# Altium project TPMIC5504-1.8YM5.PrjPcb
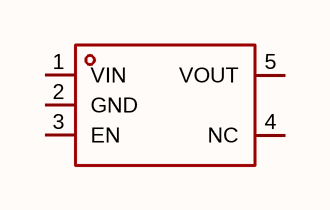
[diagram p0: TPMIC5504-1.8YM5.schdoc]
1 sheet, 1 parts. Net scope: global (net labels, ports and power ports of the same name join across sheets).

## Sheet TPMIC5504-1.8YM5.schdoc
size 127 x 101 mm

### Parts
U?  tpmic5504-1.8ym5  [SOT-23-5_L3.0-W1.5-P0.95-LS2.8-BL]  (value not drawn)

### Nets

Not connected (* = marked no-connect by the designer): U? 1(VIN) 2(GND) 3(EN) 4(NC) 5(VOUT)

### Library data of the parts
U? = tpmic5504-1.8ym5: 输出极性:正极;工作电压:5.5V;输出电压:1.8V;输出电流:300mA;电源纹波抑制比(PSRR):75dB@(1kHz);输出类型:固定;; Manufacturer: TECH PUBLIC(台舟); AddInBom: yes; ModelId: 424d41c645fb4cc2a3598f66fad27964; ModelTransform: 118.11,110.236,0,0,0,0,0,0,0; Output Configuration: 正极; Voltage - Supply: 5.5V; Output Voltage: 1.8V; Output Current: 300mA; Voltage Dropout: 280mV@(300mA); standby current: 15uA; Output Type: 固定; Number of Outputs: 1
